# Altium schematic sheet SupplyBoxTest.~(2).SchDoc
size A; SheetNumber: 1; SheetTotal: 1
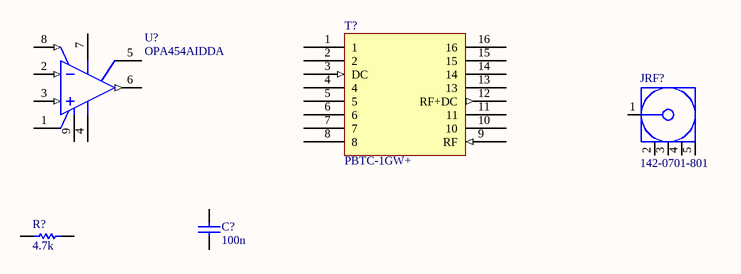
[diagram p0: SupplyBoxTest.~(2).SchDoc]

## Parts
C?  100n  [CAPC2013X145X48NL20T23]
JRF?  142-0701-801  [CINC-142-0701-801_V]
R?  4.7k  [RESC2013X60X35NL10T20]
T?  PBTC-1GW+  [PBTC-1GW+]
U?  OPA454AIDDA  [DDA0008C_L]

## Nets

Not connected (* = marked no-connect by the designer): C? 1 2; JRF? 1 2 3 4 5; R? 1 2; T? 1 2 3(DC) 4 5 6 7 8 9(RF) 10 11 12(RF+DC) 13 14 15 16; U? 1(E/D_COM) 2(IN-) 3(IN+) 4(V-) 5(STATUS_FLAG) 6(OUT) 7(V+) 8(E/D) 9(EP)

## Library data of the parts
C? = CMP-2007-03167-1: Manufacturer: Vitramon; Part Number: VJ0805Y104KNAAT
JRF? = CMP-2000-05490-1: SMA End Launch Jack Receptacle, 50 Ohm, 0 to 18 GHz, -65 to 165 degC, 5-Pin SMD, RoHS, Bulk; Manufacturer: EmersonConnectivitySolutions; Connector Type: JackPCB; Gender: Jack(Female); Impedance: 50Ohms; Brand: Johnson/EmersonConnectivitySolutions; Body Material: Brass; Body Style: Straight; Maximum Frequency: 18GHz
R? = CMP-1659-00011-4: Chip Resistor, 47 KOhm, +/- 1%, 0.125 W, -55 to 155 degC, 0805 (2012 Metric), RoHS, Tape and Reel; Manufacturer: Yageo; Voltage Rating: 150 V
T? = CMP-00025-00003-1: Monitor TEE DC Block, 0.1MHz Min, 1000MHz Max, 1dB Insertion Loss-Max
U? = CMP-0017-00714-2: High Voltage (100V), High-Current (50mA) Operational Amplifier, G=1 Stable, 10 to 100 V, -55 to 125 degC, 8-pin SOP (DDA8), Green (RoHS & no Sb/Br); Manufacturer: Texas Instruments; Number of Channels: 1; CMRR(Min)(dB): 100; Rating: Catalog; Total Supply Voltage(Min)(+5V is 5, +/-5V is 10): 10; Offset Drift(Typ)(uV/C): 1.6; Vn at 1kHz(Typ)(nV/rtHz): 47; Slew Rate(Typ)(V/us): 13; Sub Family: General Purpose Amplifier, High Output Current Amplifier (>=50mA), High Supply Voltage Amplifier (>=30V), Precision Amplifier; Iq per channel(Max)(mA): 4; GBW(Typ)(MHz): 2.5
